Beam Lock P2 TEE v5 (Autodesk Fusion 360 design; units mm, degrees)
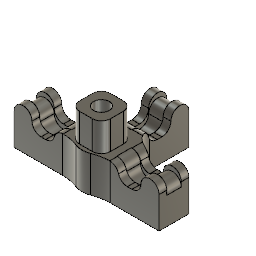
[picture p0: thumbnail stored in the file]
parameter "heatset_entry" = 5.2
parameter "heatset_depth" = 4
parameter "heatset_taperby" = 0.2
parameter "recip_thickness" = 3.2
parameter "recip_slotwidth" = 7
parameter "print_wall" = 0.435 (= "( 0.87 / 2 ) * 1 mm")
parameter "recip_distfrom" = 4.5
parameter "recip_tooth" = 1 comment "extra length to lock-in"
parameter "recip_slotdepth" = 10
sketch "Sketch1" plane through (0, 0, 0) normal (0, 0, 1) x axis (1, 0, 0)
  line L1 (-16, -1.6) -> (-12, -1.6)
  line L2 (-16, 1.6) -> (-16, -1.6)
  line L3 (-12, 1.6) -> (-16, 1.6)
  line L4 (-12, -1.6) -> (-12, 1.6)
  line L5 (0, 1.73) -> (0, 2.6)
  line L6 (0, -1.73) -> (0, -2.6)
  line L7 (0, 4.3) -> (0, 2.6)
  line L8 (0, -4.3) -> (0, -2.6)
  line L9 (-7, 1.6) -> (-12, 1.6)
  line L10 (-7, -1.6) -> (-12, -1.6)
  line L11 (-7, -1.6) -> (-7, 1.6)
  line L12 (-4, 1.6) -> (-7, 1.6)
  line L13 (-4, -1.6) -> (-4, 1.6)
  line L14 (-7, -1.6) -> (-4, -1.6)
  line L15 (-4, 3.3) -> (-4, 1.6)
  line L16 (-16, 3.3) -> (-4, 3.3)
  line L17 (-16, 1.6) -> (-16, 3.3)
  line L18 (-16, 0) -> (0, 0)
  line L19 (-12, 3.3) -> (-12, 1.6)
  line L20 (-7, 3.3) -> (-7, 1.6)
  line L21 (-2.7568, 3.3) -> (-4, 3.3)
  line L22 (3.43, -3.43) -> (-3.43, -3.43)
  line L23 (3.43, 3.43) -> (3.43, -3.43)
  line L24 (-3.43, 3.43) -> (3.43, 3.43)
  line L25 (-3.43, -3.43) -> (-3.43, 3.43)
  line L26 (3.43, 3.43) -> (-3.43, -3.43)
  line L27 (-3.43, 3.43) -> (3.43, -3.43)
  circle C1 centre (0, 0) radius 1.625
  circle C2 centre (0, 0) radius 3
  circle C3 centre (0, 0) radius 2.6
  circle C4 centre (0, 0) radius 1.73
  circle C5 centre (0, 0) radius 4.3
  point P1 (0, 0)
  point P2 (0, 0)
  point P5 (0, 0)
  point P10 (0, 2.6)
  point P11 (0, -2.6)
  point P12 (0, 1.73)
  point P13 (0, -1.73)
  point P14 (-12, 0)
  point P3 (0, 0)
  point P4 (0, 0)
  point P15 (0, 0)
  point P16 (0, 4.3)
  point P17 (0, -4.3)
  point P18 (-7, -1.6)
  point P21 (-7, -1.6)
  point P8 (-16, 1.6)
  point P24 (-16, 1.6)
  point P25 (0, 0)
  point P26 (-16, 0)
  point P27 (-12, 3.3)
  point P28 (-7, 3.3)
  point P30 (-2.7568, 3.3)
  point P35 (0, 0)
  point P36 (0, -3.43)
  point P37 (0, -1.73)
  point P7 (-16, -1.6)
  point P9 (-12, 1.6)
  point P20 (-4, -1.6)
  point P23 (-16, 3.3)
  coincident P1 P2
  concentric C1 C2
  concentric C2 C3
  coincident P1 P5
  horizontal L1
  vertical L2
  horizontal L3
  coincident C3 P10
  coincident C3 P11
  coincident C4 P12
  coincident C4 P13
  vertical L4
  midpoint L4 P14
  coincident P3 L5
  coincident P4 L6
  vertical L5
  vertical L6
  horizontal P1 P14
  coincident P1 P15
  coincident C5 P16
  vertical L7
  coincident C5 P17
  parallel L7 L8
  perpendicular L4 L9
  perpendicular L4 L10
  perpendicular L11 L12
  perpendicular L12 L13
  perpendicular L13 L14
  coincident P18 P21
  perpendicular L12 L15
  perpendicular L15 L16
  perpendicular L16 L17
  coincident P8 P24
  coincident P2 P25
  midpoint L2 P26
  coincident L16 P27
  perpendicular L16 L19
  coincident L16 P28
  perpendicular L16 L20
  vertical L20
  coincident C5 P30
  perpendicular L15 L21
  perpendicular L22 L23
  parallel L22 L24
  parallel L23 L25
  horizontal L22
  coincident L26 P35
  coincident L27 P35
  coincident P5 P35
  midpoint L22 P36
  coincident P13 P37
  equal L22 L25
  dimension "d1" diameter C1 = 3.25
  dimension "d2" diameter C2 = 6
  dimension "d3" diameter C3 = 5.2 (= "heatset_entry")
  dimension "d4" distance C3 C4 = 0.87 (= "print_wall * 2")
  dimension "d11" distance P7 P8 = 3.2 (= "recip_thickness")
  dimension "d29" distance P8 P9 = 4
  dimension "d69" distance P11 P17 = 1.7
  dimension "d70" distance L4 P18 = 5
  dimension "d71" distance P20 P21 = 3
  dimension "d72" distance P23 P24 = 1.7
  dimension "d95" distance P15 L13 = 4
  dimension "d99" distance P36 P37 = 1.7
  dimension "d104" distance P15 L22 = 3.43
extrude "Extrude7" new body sketch "Sketch1" profile of C3 C4 L2 L3 L4 L5 L6 C5 L7 L8 L9 L11 L12 L13 L14 L15 L16 L17 L18 L19 L20 L21 along normal blind 8 (= "heatset_depth + 4 mm")
extrude "Extrude9" cut sketch "Sketch1" profile of C3 C4 L5 L6 L18 along normal blind 4 (= "heatset_depth")
chamfer "Chamfer8" distance 0.2 (= "heatset_taperby") distance 4 (= "heatset_depth")
chamfer "Chamfer9" distance 0.4
extrude "Extrude8" sketch "Sketch1" profile of L4 C5 L9 L11 L16 L18 L19 L20 blind -4
extrude "Extrude10" sketch "Sketch1" profile of L9 L16 L19 L20 blind 1
extrude "Extrude11" sketch "Sketch1" profile of L3 L16 L17 L19 blind 1
fillet "Fillet12" radius 2
fillet "Fillet13" radius 2
fillet "Fillet14" radius 10
mirror "Mirror2"
combine "Combine2"
chamfer "Chamfer10" distance 0.87
copy_paste_bodies "CopyPasteBodies2"
move "Move2"
mirror "Mirror4"
combine "Combine5"
extrude "Extrude12" sketch "Sketch1" profile of C3 C4 L5 L6 C5 L7 L8 L18 L21 L22 L23 L24 L25 blind 6.25
fillet "Fillet17" radius 2
fillet "Fillet18" radius 4
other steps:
base_feature "Base Feature"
